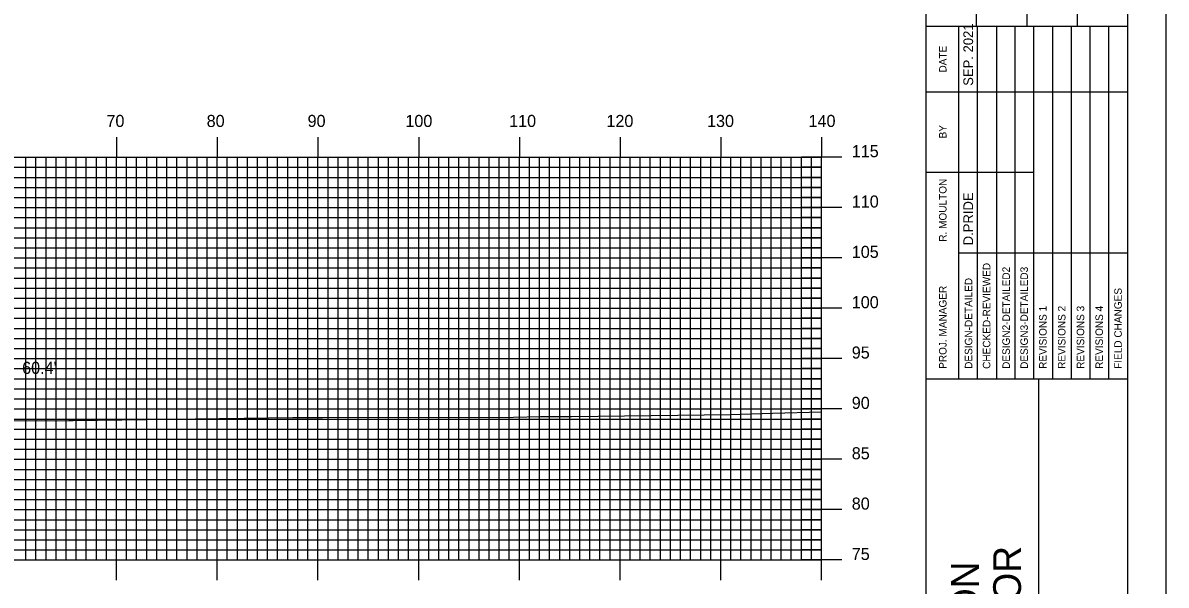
# Model space of a CAD drawing. Extents: x 1760217 to 1760560, y 442591 to 442811.
# Drawn here: x 1760443.4 to 1760556.9, y 442666.2 to 442722 of the extents above; entities that cross this region are included whole.
import ezdxf

# ---------------------------------------------------------------- set-up
doc = ezdxf.new("R2010")
doc.units = 0
for name, color, linetype in [('BORDER', 7, 'Continuous'), ('D_Text_Standard', 7, 'Continuous'), ('H_V ANNOTATION', 7, 'Continuous'), ('MAJOR', 7, 'Continuous'), ('MINOR', 7, 'Continuous'), ('PLOT BOUNDARY', 7, 'Continuous'), ('S_Roadway_Centerline', 7, 'Continuous')]:
    doc.layers.add(name, color=color, linetype=linetype)

msp = doc.modelspace()

# ---------------------------------------------------------------- linework, layer by layer
at = {"layer": 'BORDER'}
for p, q in [((1760533.1, 442596.67), (1760533.1, 442806.67)), ((1760538.1, 442721.67), (1760538.1, 442738.97)), ((1760543.1, 442721.67), (1760543.1, 442738.97)), ((1760548.1, 442721.67), (1760548.1, 442738.97)), ((1760533.1, 442721.67), (1760553.1, 442721.67)), ((1760533.1, 442686.67), (1760553.1, 442686.67)), ((1760544.28, 442616.67), (1760544.28, 442686.67))]:
    msp.add_line(p, q, dxfattribs=at)
msp.add_lwpolyline([(1760233.1, 442596.67), (1760553.1, 442596.67), (1760553.1, 442806.67), (1760233.1, 442806.67)], close=True, dxfattribs=at)
for points in [[(1760536.33, 442715.17), (1760536.33, 442721.67)], [(1760538.2, 442686.68), (1760538.2, 442721.67)], [(1760540.06, 442721.67), (1760540.06, 442686.68)], [(1760541.92, 442686.68), (1760541.92, 442721.67)], [(1760543.79, 442686.68), (1760543.79, 442721.67)], [(1760545.65, 442686.68), (1760545.65, 442721.67)], [(1760547.51, 442686.68), (1760547.51, 442721.67)], [(1760549.38, 442686.68), (1760549.38, 442721.67)], [(1760551.24, 442686.68), (1760551.24, 442721.67)], [(1760536.33, 442686.68), (1760536.33, 442720.26)], [(1760533.1, 442715.17), (1760553.1, 442715.17)], [(1760533.1, 442707.17), (1760536.33, 442707.17)], [(1760536.33, 442707.17), (1760543.78, 442707.17)], [(1760536.33, 442699.17), (1760553.1, 442699.17)]]:
    msp.add_lwpolyline(points, dxfattribs=at)
at = {"layer": 'MAJOR'}
for p, q in [((1760452.7, 442710.67), (1760452.7, 442708.67)), ((1760462.7, 442710.67), (1760462.7, 442708.67)), ((1760472.7, 442710.67), (1760472.7, 442708.67)), ((1760482.7, 442710.67), (1760482.7, 442708.67)), ((1760492.7, 442710.67), (1760492.7, 442708.67)), ((1760502.7, 442710.67), (1760502.7, 442708.67)), ((1760512.7, 442710.67), (1760512.7, 442708.67)), ((1760522.7, 442710.67), (1760522.7, 442708.67)), ((1760242.7, 442708.67), (1760522.7, 442708.67)), ((1760242.7, 442708.67), (1760522.7, 442708.67)), ((1760452.7, 442668.67), (1760452.7, 442708.67)), ((1760462.7, 442668.67), (1760462.7, 442708.67)), ((1760472.7, 442668.67), (1760472.7, 442708.67)), ((1760482.7, 442668.67), (1760482.7, 442708.67)), ((1760492.7, 442668.67), (1760492.7, 442708.67)), ((1760502.7, 442668.67), (1760502.7, 442708.67)), ((1760512.7, 442668.67), (1760512.7, 442708.67)), ((1760524.7, 442708.67), (1760520.7, 442708.67)), ((1760522.7, 442668.67), (1760522.7, 442708.67)), ((1760522.7, 442668.67), (1760522.7, 442708.67)), ((1760242.7, 442703.67), (1760522.7, 442703.67)), ((1760524.7, 442703.67), (1760520.7, 442703.67)), ((1760242.7, 442698.67), (1760522.7, 442698.67)), ((1760524.7, 442698.67), (1760520.7, 442698.67)), ((1760242.7, 442693.67), (1760522.7, 442693.67)), ((1760524.7, 442693.67), (1760520.7, 442693.67)), ((1760242.7, 442688.67), (1760522.7, 442688.67)), ((1760524.7, 442688.67), (1760520.7, 442688.67)), ((1760242.7, 442683.67), (1760522.7, 442683.67)), ((1760524.7, 442683.67), (1760520.7, 442683.67)), ((1760242.7, 442678.67), (1760522.7, 442678.67)), ((1760524.7, 442678.67), (1760520.7, 442678.67)), ((1760242.7, 442673.67), (1760522.7, 442673.67)), ((1760524.7, 442673.67), (1760520.7, 442673.67)), ((1760242.7, 442668.67), (1760522.7, 442668.67)), ((1760242.7, 442668.67), (1760522.7, 442668.67)), ((1760452.7, 442666.66), (1760452.7, 442668.67)), ((1760462.7, 442666.66), (1760462.7, 442668.67)), ((1760472.7, 442666.66), (1760472.7, 442668.67)), ((1760482.7, 442666.66), (1760482.7, 442668.67)), ((1760492.7, 442666.66), (1760492.7, 442668.67)), ((1760502.7, 442666.66), (1760502.7, 442668.67)), ((1760512.7, 442666.66), (1760512.7, 442668.67)), ((1760524.7, 442668.67), (1760520.7, 442668.67)), ((1760522.7, 442666.66), (1760522.7, 442668.67))]:
    msp.add_line(p, q, dxfattribs=at)
at = {"layer": 'MINOR'}
for p, q in [((1760242.7, 442707.67), (1760522.7, 442707.67)), ((1760443.7, 442668.67), (1760443.7, 442708.67)), ((1760444.7, 442668.67), (1760444.7, 442708.67)), ((1760445.7, 442668.67), (1760445.7, 442708.67)), ((1760446.7, 442668.67), (1760446.7, 442708.67)), ((1760447.7, 442668.67), (1760447.7, 442708.67)), ((1760448.7, 442668.67), (1760448.7, 442708.67)), ((1760449.7, 442668.67), (1760449.7, 442708.67)), ((1760450.7, 442668.67), (1760450.7, 442708.67)), ((1760451.7, 442668.67), (1760451.7, 442708.67)), ((1760453.7, 442668.67), (1760453.7, 442708.67)), ((1760454.7, 442668.67), (1760454.7, 442708.67)), ((1760455.7, 442668.67), (1760455.7, 442708.67)), ((1760456.7, 442668.67), (1760456.7, 442708.67)), ((1760457.7, 442668.67), (1760457.7, 442708.67)), ((1760458.7, 442668.67), (1760458.7, 442708.67)), ((1760459.7, 442668.67), (1760459.7, 442708.67)), ((1760460.7, 442668.67), (1760460.7, 442708.67)), ((1760461.7, 442668.67), (1760461.7, 442708.67)), ((1760463.7, 442668.67), (1760463.7, 442708.67)), ((1760464.7, 442668.67), (1760464.7, 442708.67)), ((1760465.7, 442668.67), (1760465.7, 442708.67)), ((1760466.7, 442668.67), (1760466.7, 442708.67)), ((1760467.7, 442668.67), (1760467.7, 442708.67)), ((1760468.7, 442668.67), (1760468.7, 442708.67)), ((1760469.7, 442668.67), (1760469.7, 442708.67)), ((1760470.7, 442668.67), (1760470.7, 442708.67)), ((1760471.7, 442668.67), (1760471.7, 442708.67)), ((1760473.7, 442668.67), (1760473.7, 442708.67)), ((1760474.7, 442668.67), (1760474.7, 442708.67)), ((1760475.7, 442668.67), (1760475.7, 442708.67)), ((1760476.7, 442668.67), (1760476.7, 442708.67)), ((1760477.7, 442668.67), (1760477.7, 442708.67)), ((1760478.7, 442668.67), (1760478.7, 442708.67)), ((1760479.7, 442668.67), (1760479.7, 442708.67)), ((1760480.7, 442668.67), (1760480.7, 442708.67)), ((1760481.7, 442668.67), (1760481.7, 442708.67)), ((1760483.7, 442668.67), (1760483.7, 442708.67)), ((1760484.7, 442668.67), (1760484.7, 442708.67)), ((1760485.7, 442668.67), (1760485.7, 442708.67)), ((1760486.7, 442668.67), (1760486.7, 442708.67)), ((1760487.7, 442668.67), (1760487.7, 442708.67)), ((1760488.7, 442668.67), (1760488.7, 442708.67)), ((1760489.7, 442668.67), (1760489.7, 442708.67)), ((1760490.7, 442668.67), (1760490.7, 442708.67)), ((1760491.7, 442668.67), (1760491.7, 442708.67)), ((1760493.7, 442668.67), (1760493.7, 442708.67)), ((1760494.7, 442668.67), (1760494.7, 442708.67)), ((1760495.7, 442668.67), (1760495.7, 442708.67)), ((1760496.7, 442668.67), (1760496.7, 442708.67)), ((1760497.7, 442668.67), (1760497.7, 442708.67)), ((1760498.7, 442668.67), (1760498.7, 442708.67)), ((1760499.7, 442668.67), (1760499.7, 442708.67)), ((1760500.7, 442668.67), (1760500.7, 442708.67)), ((1760501.7, 442668.67), (1760501.7, 442708.67)), ((1760503.7, 442668.67), (1760503.7, 442708.67)), ((1760504.7, 442668.67), (1760504.7, 442708.67)), ((1760505.7, 442668.67), (1760505.7, 442708.67)), ((1760506.7, 442668.67), (1760506.7, 442708.67)), ((1760507.7, 442668.67), (1760507.7, 442708.67)), ((1760508.7, 442668.67), (1760508.7, 442708.67)), ((1760509.7, 442668.67), (1760509.7, 442708.67)), ((1760510.7, 442668.67), (1760510.7, 442708.67)), ((1760511.7, 442668.67), (1760511.7, 442708.67)), ((1760513.7, 442668.67), (1760513.7, 442708.67)), ((1760514.7, 442668.67), (1760514.7, 442708.67)), ((1760515.7, 442668.67), (1760515.7, 442708.67)), ((1760516.7, 442668.67), (1760516.7, 442708.67)), ((1760517.7, 442668.67), (1760517.7, 442708.67)), ((1760518.7, 442668.67), (1760518.7, 442708.67)), ((1760519.7, 442668.67), (1760519.7, 442708.67)), ((1760520.7, 442668.67), (1760520.7, 442708.67)), ((1760522.7, 442707.67), (1760520.7, 442707.67)), ((1760521.7, 442668.67), (1760521.7, 442708.67)), ((1760242.7, 442706.67), (1760522.7, 442706.67)), ((1760522.7, 442706.67), (1760520.7, 442706.67)), ((1760242.7, 442705.67), (1760522.7, 442705.67)), ((1760522.7, 442705.67), (1760520.7, 442705.67)), ((1760242.7, 442704.67), (1760522.7, 442704.67)), ((1760522.7, 442704.67), (1760520.7, 442704.67)), ((1760242.7, 442702.67), (1760522.7, 442702.67)), ((1760522.7, 442702.67), (1760520.7, 442702.67)), ((1760242.7, 442701.67), (1760522.7, 442701.67)), ((1760522.7, 442701.67), (1760520.7, 442701.67)), ((1760242.7, 442700.67), (1760522.7, 442700.67)), ((1760242.7, 442699.67), (1760522.7, 442699.67)), ((1760522.7, 442700.67), (1760520.7, 442700.67)), ((1760522.7, 442699.67), (1760520.7, 442699.67)), ((1760242.7, 442697.67), (1760522.7, 442697.67)), ((1760522.7, 442697.67), (1760520.7, 442697.67)), ((1760242.7, 442696.67), (1760522.7, 442696.67)), ((1760522.7, 442696.67), (1760520.7, 442696.67)), ((1760242.7, 442695.67), (1760522.7, 442695.67)), ((1760522.7, 442695.67), (1760520.7, 442695.67)), ((1760242.7, 442694.67), (1760522.7, 442694.67)), ((1760522.7, 442694.67), (1760520.7, 442694.67)), ((1760242.7, 442692.67), (1760522.7, 442692.67)), ((1760522.7, 442692.67), (1760520.7, 442692.67)), ((1760242.7, 442691.67), (1760522.7, 442691.67)), ((1760242.7, 442690.67), (1760522.7, 442690.67)), ((1760522.7, 442691.67), (1760520.7, 442691.67)), ((1760522.7, 442690.67), (1760520.7, 442690.67)), ((1760242.7, 442689.67), (1760522.7, 442689.67)), ((1760522.7, 442689.67), (1760520.7, 442689.67)), ((1760242.7, 442687.67), (1760522.7, 442687.67)), ((1760522.7, 442687.67), (1760520.7, 442687.67)), ((1760242.7, 442686.67), (1760522.7, 442686.67)), ((1760522.7, 442686.67), (1760520.7, 442686.67)), ((1760242.7, 442685.67), (1760522.7, 442685.67)), ((1760522.7, 442685.67), (1760520.7, 442685.67)), ((1760242.7, 442684.67), (1760522.7, 442684.67)), ((1760522.7, 442684.67), (1760520.7, 442684.67)), ((1760242.7, 442682.67), (1760522.7, 442682.67)), ((1760522.7, 442682.67), (1760520.7, 442682.67)), ((1760242.7, 442681.67), (1760522.7, 442681.67)), ((1760522.7, 442681.67), (1760520.7, 442681.67)), ((1760242.7, 442680.67), (1760522.7, 442680.67)), ((1760522.7, 442680.67), (1760520.7, 442680.67)), ((1760242.7, 442679.67), (1760522.7, 442679.67)), ((1760522.7, 442679.67), (1760520.7, 442679.67)), ((1760242.7, 442677.67), (1760522.7, 442677.67)), ((1760522.7, 442677.67), (1760520.7, 442677.67)), ((1760242.7, 442676.67), (1760522.7, 442676.67)), ((1760522.7, 442676.67), (1760520.7, 442676.67)), ((1760242.7, 442675.67), (1760522.7, 442675.67)), ((1760522.7, 442675.67), (1760520.7, 442675.67)), ((1760242.7, 442674.67), (1760522.7, 442674.67)), ((1760522.7, 442674.67), (1760520.7, 442674.67)), ((1760242.7, 442672.67), (1760522.7, 442672.67)), ((1760522.7, 442672.67), (1760520.7, 442672.67)), ((1760242.7, 442671.67), (1760522.7, 442671.67)), ((1760522.7, 442671.67), (1760520.7, 442671.67)), ((1760242.7, 442670.67), (1760522.7, 442670.67)), ((1760522.7, 442670.67), (1760520.7, 442670.67)), ((1760242.7, 442669.67), (1760522.7, 442669.67)), ((1760522.7, 442669.67), (1760520.7, 442669.67))]:
    msp.add_line(p, q, dxfattribs=at)
at = {"layer": 'PLOT BOUNDARY'}
msp.add_lwpolyline([(1760216.91, 442590.55), (1760556.91, 442590.55), (1760556.91, 442810.55), (1760216.91, 442810.55)], close=True, dxfattribs=at)
at = {"layer": 'S_Roadway_Centerline'}
msp.add_lwpolyline([(1760438.56, 442682.49), (1760447.95, 442682.51), (1760448.19, 442682.51), (1760448.29, 442682.51), (1760448.4, 442682.52), (1760470.21, 442682.83), (1760473.14, 442682.82), (1760492.1, 442682.86), (1760494.8, 442682.92), (1760497.86, 442682.92), (1760513.69, 442683.11), (1760517.84, 442683.25), (1760522.7, 442683.37)], dxfattribs=at)

# ---------------------------------------------------------------- texts
at = {"layer": 'BORDER'}
for s, height, p in [('SEP. 2021', 0.969, (1760537.75, 442715.76)), ('DATE', 0.743, (1760535.11, 442717.08)), ('BY', 0.743, (1760535.11, 442710.54)), ('R. MOULTON', 0.745, (1760535.11, 442700.28)), ('D.PRIDE', 0.969, (1760537.75, 442699.92)), ('CHECKED-REVIEWED', 0.7455, (1760539.46, 442687.65)), ('DESIGN2-DETAILED2', 0.7455, (1760541.4, 442687.65)), ('DESIGN3-DETAILED3', 0.7455, (1760543.19, 442687.65)), ('DESIGN-DETAILED', 0.7455, (1760537.67, 442687.65)), ('PROJ. MANAGER', 0.7455, (1760535.11, 442687.65)), ('FIELD CHANGES', 0.7455, (1760552.51, 442687.65)), ('REVISIONS 1', 0.7455, (1760545.05, 442687.65)), ('REVISIONS 2', 0.7455, (1760546.92, 442687.65)), ('REVISIONS 3', 0.7455, (1760548.78, 442687.65)), ('REVISIONS 4', 0.7455, (1760550.64, 442687.65)), ('1-395/ROUTE 9 CONNECTOR', 2.7557, (1760542.5, 442618.87)), ('BREWER TO EDDINGTON', 2.7557, (1760538.32, 442623.07))]:
    msp.add_text(s, height=height, rotation=90, dxfattribs=at).set_placement(p)
at = {"layer": 'D_Text_Standard'}
msp.add_text("60.4'", height=1.2, dxfattribs=at).set_placement((1760443.33, 442687.15))
at = {"layer": 'H_V ANNOTATION'}
for s, p in [('70', (1760451.7, 442711.67)), ('80', (1760461.65, 442711.67)), ('90', (1760471.67, 442711.67)), ('100', (1760481.38, 442711.67)), ('110', (1760491.68, 442711.67)), ('120', (1760501.34, 442711.67)), ('130', (1760511.33, 442711.67)), ('140', (1760521.41, 442711.67)), ('115', (1760525.7, 442708.67)), ('110', (1760525.7, 442703.67)), ('105', (1760525.7, 442698.67)), ('100', (1760525.7, 442693.67)), ('95', (1760525.7, 442688.67)), ('90', (1760525.7, 442683.67)), ('85', (1760525.7, 442678.67)), ('80', (1760525.7, 442673.67)), ('75', (1760525.7, 442668.67))]:
    msp.add_text(s, height=1.2, dxfattribs=at).set_placement(p)

doc.saveas('drawing.dxf')
